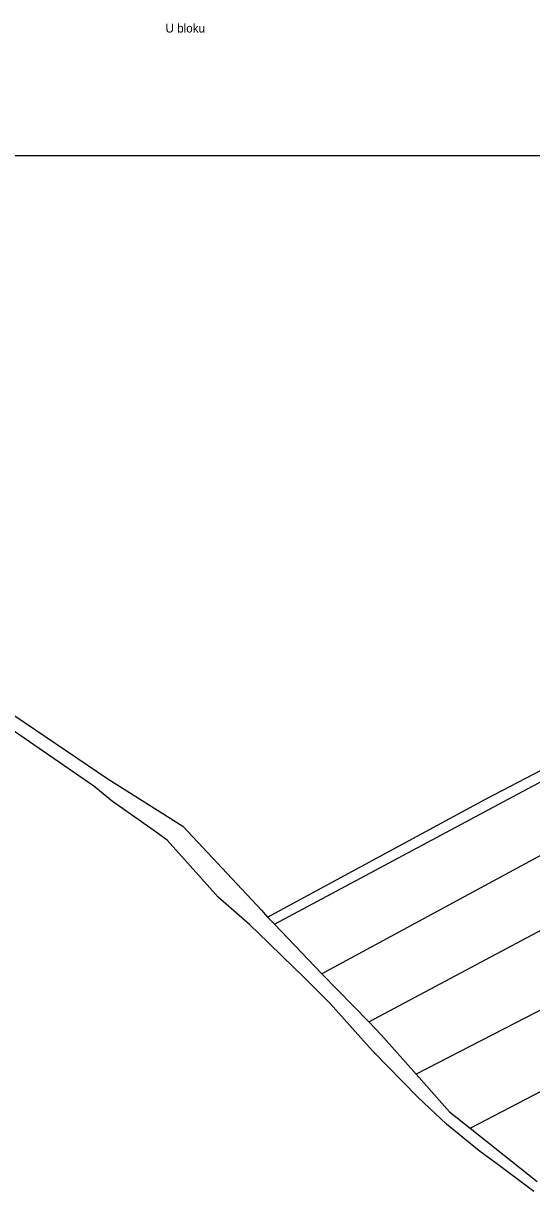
# Model space of a CAD drawing. Extents: x -780000 to -777378, y -1011169 to -1009297.
# Drawn here: x -778667 to -778410, y -1011023 to -1010433 of the extents above; entities that cross this region are included whole.
import ezdxf

# ---------------------------------------------------------------- set-up
doc = ezdxf.new("R2010")
doc.units = 0
for name, color, linetype in [('KLADY_ZMVM', 7, 'Continuous'), ('KN_HRANICE', 7, 'Continuous'), ('KN_PARCELY', 7, 'Continuous')]:
    doc.layers.add(name, color=color, linetype=linetype)

msp = doc.modelspace()

# ---------------------------------------------------------------- linework, layer by layer
at = {"layer": 'KLADY_ZMVM'}
msp.add_lwpolyline([(-778750, -1011000), (-778750, -1010500), (-778125, -1010500)], dxfattribs=at)
at = {"layer": 'KN_HRANICE'}
for p, q in [((-778412.34, -1010819.61), (-778282.98, -1010750.53)), ((-778676.79, -1010778.85), (-778624.16, -1010814.46)), ((-778631.26, -1010818.25), (-778679.13, -1010785.37)), ((-778433.26, -1010824.65), (-778357.59, -1010785.18)), ((-778621.86, -1010825.98), (-778631.26, -1010818.25)), ((-778624.16, -1010814.46), (-778586.31, -1010838.48)), ((-778540.08, -1010887.83), (-778412.34, -1010819.61)), ((-778601.01, -1010840.56), (-778621.86, -1010825.98)), ((-778543.66, -1010884.4), (-778433.26, -1010824.65)), ((-778594.3, -1010845.53), (-778601.01, -1010840.56)), ((-778586.31, -1010838.48), (-778546.61, -1010880.74)), ((-778578.28, -1010863.29), (-778594.3, -1010845.53)), ((-778392.34, -1010845.85), (-778516.11, -1010912.84)), ((-778568.44, -1010874.2), (-778578.28, -1010863.29)), ((-778556.56, -1010884.61), (-778568.44, -1010874.2)), ((-778492.42, -1010937.08), (-778372.93, -1010873.38)), ((-778552.44, -1010888.22), (-778556.56, -1010884.61)), ((-778546.61, -1010880.74), (-778543.66, -1010884.4)), ((-778543.66, -1010884.4), (-778540.08, -1010887.83)), ((-778543.31, -1010897.11), (-778552.44, -1010888.22)), ((-778540.08, -1010887.83), (-778516.11, -1010912.84)), ((-778535.87, -1010904.34), (-778543.31, -1010897.11)), ((-778525.77, -1010914.17), (-778535.87, -1010904.34)), ((-778511.84, -1010928.07), (-778525.77, -1010914.17)), ((-778516.11, -1010912.84), (-778492.42, -1010937.08)), ((-778380.28, -1010918.01), (-778468.57, -1010963.46)), ((-778495.13, -1010946.65), (-778511.84, -1010928.07)), ((-778492.42, -1010937.08), (-778486.13, -1010943.65)), ((-778486.13, -1010943.65), (-778468.57, -1010963.46)), ((-778490.52, -1010951.78), (-778495.13, -1010946.65)), ((-778441.21, -1010990.73), (-778362.13, -1010949.54)), ((-778467.75, -1010975.19), (-778490.52, -1010951.78)), ((-778468.57, -1010963.46), (-778451.73, -1010982.61)), ((-778453.23, -1010988.79), (-778467.75, -1010975.19)), ((-778451.73, -1010982.61), (-778441.21, -1010990.73)), ((-778436.69, -1011002.15), (-778453.23, -1010988.79)), ((-778441.21, -1010990.73), (-778407.53, -1011017.65)), ((-778427.3, -1011009.18), (-778436.69, -1011002.15)), ((-778409.1, -1011022.81), (-778427.3, -1011009.18))]:
    msp.add_line(p, q, dxfattribs=at)

# ---------------------------------------------------------------- texts
at = {"layer": 'KN_PARCELY'}
msp.add_text('U bloku', height=4.4, dxfattribs=at).set_placement((-778595.08, -1010438))

doc.saveas('drawing.dxf')
